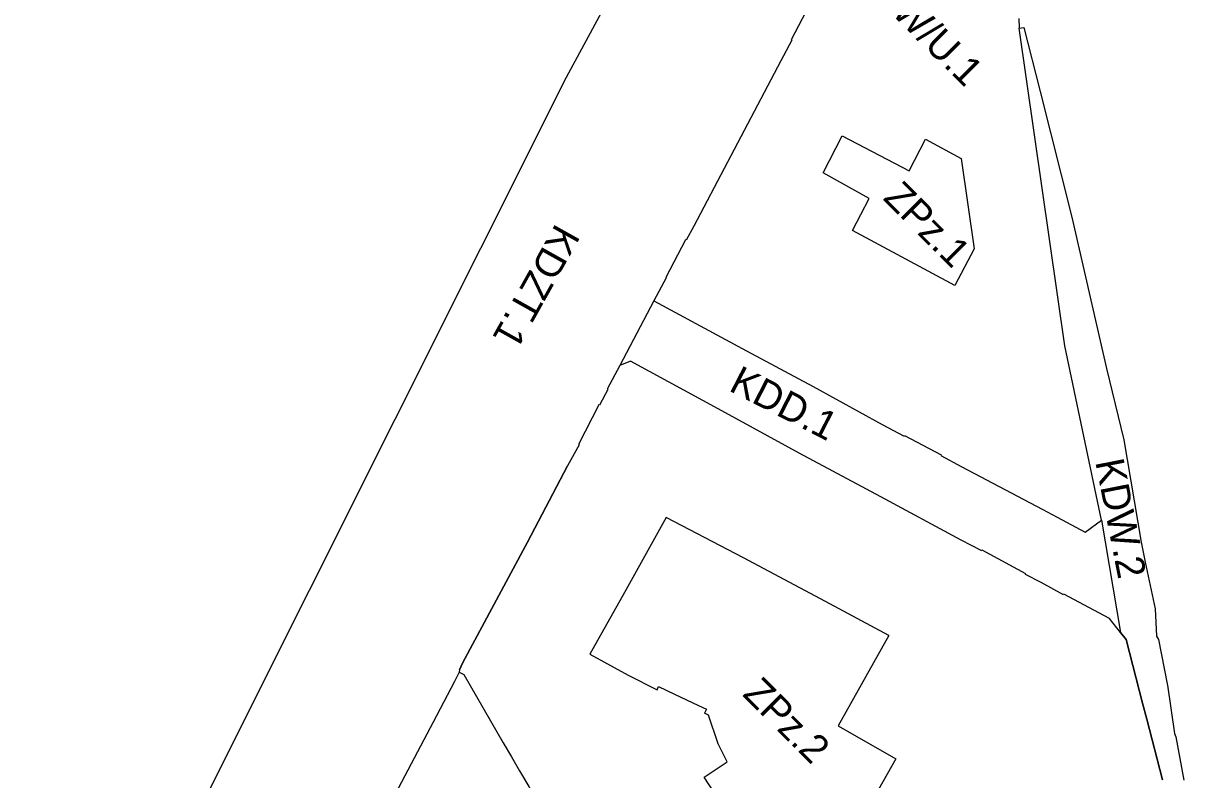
# Model space of a CAD drawing. Extents: x 7423835 to 7425280, y 5546086 to 5547600.
# Drawn here: x 7424423.3 to 7424667.5, y 5547201.6 to 5547360.7 of the extents above; entities that cross this region are included whole.
import ezdxf

# ---------------------------------------------------------------- set-up
doc = ezdxf.new("R2010")
doc.units = 0
for name, color, linetype in [('linie rozgraniczające', 7, 'Continuous'), ('nieprzekraczalne linie zabudowy', 7, 'Continuous'), ('obowiazujace linie zabudowy', 7, 'Continuous'), ('przeznaczenia terenów', 7, 'Continuous')]:
    doc.layers.add(name, color=color, linetype=linetype)

msp = doc.modelspace()

# ---------------------------------------------------------------- linework, layer by layer
at = {"layer": 'linie rozgraniczające'}
for p, q in [((7424483.52, 5547241.43), (7424537.6, 5547349.36)), ((7424555.99, 5547302.27), (7424548.85, 5547288.7)), ((7424421.63, 5547117.9), (7424483.52, 5547241.43))]:
    msp.add_line(p, q, dxfattribs=at)
for points in [[(7424537.6, 5547349.36), (7424562.07, 5547394.62), (7424577.11, 5547416.18)], [(7424589.6, 5547366.25), (7424584.84, 5547357.21), (7424585.01, 5547357.12), (7424582.67, 5547352.76), (7424571.47, 5547331.48), (7424564.36, 5547318.01), (7424562.77, 5547315.08), (7424562.63, 5547315.15), (7424558.47, 5547307.23), (7424558.58, 5547307.15), (7424555.99, 5547302.27), (7424575.46, 5547291.81), (7424589.5, 5547284.29), (7424604.04, 5547276.28), (7424608.67, 5547273.81), (7424608.73, 5547273.94), (7424616.41, 5547269.87), (7424616.37, 5547269.73), (7424620.75, 5547267.4), (7424637.66, 5547258.5), (7424640.87, 5547256.8), (7424646.74, 5547253.63), (7424650.15, 5547256.19)], [(7424632.77, 5547361.71), (7424632.86, 5547359.66), (7424633.83, 5547359.78), (7424637.24, 5547346.34), (7424643.9, 5547319.87), (7424651.24, 5547288.03), (7424654.85, 5547273.04), (7424658.53, 5547251.56), (7424658.67, 5547250.84), (7424659.32, 5547247.35), (7424661.49, 5547237.51), (7424661.75, 5547231.8), (7424662.18, 5547231.05), (7424663.95, 5547221.73), (7424664.07, 5547221.44), (7424665.5, 5547211.3), (7424665.83, 5547210.62), (7424667.48, 5547201.5)], [(7424650.15, 5547256.19), (7424642.43, 5547292.82), (7424632.86, 5547359.66)], [(7424654.13, 5547232.56), (7424651.82, 5547235.47), (7424642.27, 5547240.57), (7424642.19, 5547240.43), (7424637.45, 5547243.02), (7424634.2, 5547244.77), (7424634.27, 5547244.89), (7424625.03, 5547249.82), (7424624.96, 5547249.69), (7424620.67, 5547251.93), (7424603.71, 5547261.07), (7424586.57, 5547270.29), (7424570.25, 5547279.16), (7424551.07, 5547289.59), (7424548.85, 5547288.7), (7424546.16, 5547283.7), (7424546.3, 5547283.62), (7424544.57, 5547280.36), (7424544.39, 5547280.44), (7424540.1, 5547272.11), (7424540.24, 5547272.04), (7424537.82, 5547267.61)], [(7424515.06, 5547224.71), (7424515.77, 5547226.25), (7424522.39, 5547238.48), (7424529.41, 5547251.56), (7424537.82, 5547267.61)], [(7424558.6, 5547256.73), (7424549.78, 5547240.94), (7424542.54, 5547227.97)], [(7424605.39, 5547231.92), (7424592.12, 5547239.05), (7424574.87, 5547248.21), (7424558.6, 5547256.73)], [(7424650.15, 5547256.19), (7424654.13, 5547232.56), (7424655.34, 5547231.03), (7424658.81, 5547217.69), (7424659.68, 5547214.33), (7424663, 5547201.56)], [(7424605.39, 5547231.92), (7424594.76, 5547212.93), (7424606.91, 5547205.94)], [(7424542.54, 5547227.97), (7424550.56, 5547223.54), (7424556.66, 5547220.51), (7424556.97, 5547221.18), (7424560.33, 5547219.58), (7424565.38, 5547217.18), (7424567.04, 5547216.39), (7424566.64, 5547215.54)], [(7424515.02, 5547224.22), (7424514.03, 5547222.22), (7424510.28, 5547215.04), (7424500.2, 5547195.98), (7424496.14, 5547188.61)], [(7424515.06, 5547224.71), (7424515.02, 5547224.22), (7424515.98, 5547223.73), (7424524.29, 5547209.32), (7424526.02, 5547206.37), (7424527.74, 5547203.41), (7424529.66, 5547200.13), (7424531.58, 5547196.85), (7424531.58, 5547196.85), (7424527.83, 5547191.15), (7424529.92, 5547182.06), (7424530.79, 5547180.62)], [(7424589.68, 5547178.04), (7424589.68, 5547178.04), (7424584.25, 5547186.11), (7424578.98, 5547183.11), (7424566.55, 5547202.13), (7424571.43, 5547205.35), (7424569.51, 5547209.13), (7424567.47, 5547215.13), (7424566.64, 5547215.54), (7424566.64, 5547215.54)], [(7424606.91, 5547205.94), (7424598.05, 5547190.36)]]:
    msp.add_lwpolyline(points, dxfattribs=at)
msp.add_lwpolyline([(7424613.16, 5547336.31), (7424620.62, 5547332.23), (7424623.35, 5547313.21), (7424619.31, 5547305.49), (7424597.74, 5547317.12), (7424601.28, 5547323.84), (7424591.57, 5547329.21), (7424595.62, 5547337), (7424609.67, 5547329.67)], close=True, dxfattribs=at)
at = {"layer": 'nieprzekraczalne linie zabudowy'}
for points in [[(7424650.15, 5547256.19), (7424642.43, 5547292.82), (7424632.86, 5547359.66)], [(7424663, 5547201.56), (7424659.68, 5547214.33), (7424658.81, 5547217.69), (7424655.34, 5547231.03), (7424654.13, 5547232.56)]]:
    msp.add_lwpolyline(points, dxfattribs=at)
at = {"layer": 'obowiazujace linie zabudowy'}
for points in [[(7424589.6, 5547366.25), (7424584.84, 5547357.21), (7424585.01, 5547357.12), (7424582.67, 5547352.76), (7424571.47, 5547331.48), (7424564.36, 5547318.01), (7424562.77, 5547315.08), (7424562.63, 5547315.15), (7424558.47, 5547307.23), (7424558.58, 5547307.15), (7424555.99, 5547302.27), (7424575.46, 5547291.81), (7424589.5, 5547284.29), (7424604.04, 5547276.28), (7424608.67, 5547273.81), (7424608.73, 5547273.94), (7424616.41, 5547269.87), (7424616.37, 5547269.73), (7424620.75, 5547267.4), (7424637.66, 5547258.5), (7424640.87, 5547256.8), (7424646.74, 5547253.63), (7424650.15, 5547256.19)], [(7424654.13, 5547232.56), (7424651.82, 5547235.47), (7424642.27, 5547240.57), (7424642.19, 5547240.43), (7424637.45, 5547243.02), (7424634.2, 5547244.77), (7424634.27, 5547244.89), (7424625.03, 5547249.82), (7424624.96, 5547249.69), (7424620.67, 5547251.93), (7424603.71, 5547261.07), (7424586.57, 5547270.29), (7424570.25, 5547279.16), (7424551.07, 5547289.59), (7424548.85, 5547288.7), (7424546.16, 5547283.7), (7424546.3, 5547283.62), (7424544.57, 5547280.36), (7424544.39, 5547280.44), (7424540.1, 5547272.11), (7424540.24, 5547272.04), (7424537.82, 5547267.61)], [(7424537.82, 5547267.61), (7424529.41, 5547251.56), (7424522.39, 5547238.48), (7424515.77, 5547226.25), (7424515.06, 5547224.71)], [(7424515.06, 5547224.71), (7424515.02, 5547224.22), (7424515.98, 5547223.73), (7424524.29, 5547209.32), (7424526.02, 5547206.37), (7424527.74, 5547203.41), (7424529.66, 5547200.13), (7424531.58, 5547196.85), (7424531.58, 5547196.85), (7424527.83, 5547191.15), (7424529.92, 5547182.06), (7424530.79, 5547180.62)]]:
    msp.add_lwpolyline(points, dxfattribs=at)

# ---------------------------------------------------------------- texts
at = {"layer": 'przeznaczenia terenów'}
for s, rotation, p in [('MW/U.1', 314.9764, (7424601.01, 5547367.52)), ('ZPz.1', 314.9764, (7424604.01, 5547323.72)), ('KDZT.1', 240.7924, (7424535.39, 5547318.79)), ('KDD.1', 332.8177, (7424571.53, 5547283.51)), ('KDW.2', 281.1257, (7424648.84, 5547268.48)), ('ZPz.2', 314.9764, (7424574.43, 5547219.37))]:
    msp.add_text(s, height=6, rotation=rotation, dxfattribs=at).set_placement(p)

doc.saveas('drawing.dxf')
